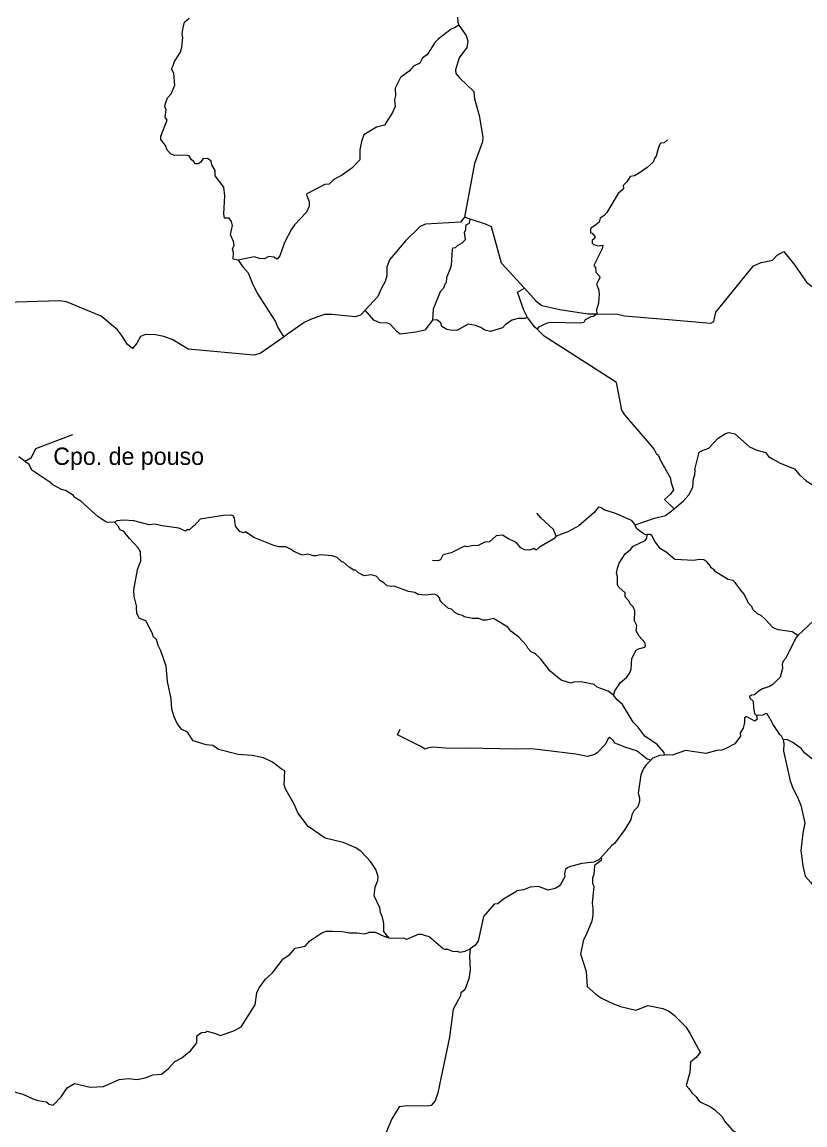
# Model space of a CAD drawing. Extents: x 332 to 501, y 9447 to 9559.
# Drawn here: x 422 to 439.16, y 9472.84 to 9497.01 of the extents above; entities that cross this region are included whole.
import ezdxf

# ---------------------------------------------------------------- set-up
doc = ezdxf.new("R2010")
doc.units = 0
for name, color, linetype in [('Level 1', 7, 'Continuous'), ('Level 13', 7, 'Continuous'), ('Level 4', 7, 'Continuous'), ('Level 5', 7, 'Continuous'), ('Level 6', 7, 'Continuous')]:
    doc.layers.add(name, color=color, linetype=linetype)

msp = doc.modelspace()

# ---------------------------------------------------------------- linework, layer by layer
at = {"layer": 'Level 1'}
msp.add_lwpolyline([(422.3073, 9487.6686), (423.1175, 9487.9761)], dxfattribs=at)
at = {"layer": 'Level 4'}
for points in [[(431.703, 9492.7355), (431.612, 9492.629), (430.848, 9492.58), (430.727, 9492.534), (430.404, 9492.217), (430.059, 9491.799), (429.995, 9491.644), (429.999, 9491.454), (429.96, 9491.327), (429.87, 9491.167), (429.801, 9490.999), (429.5223, 9490.6969)], [(431.8221, 9492.6961), (431.703, 9492.7355)], [(433.0134, 9491.1786), (432.512, 9491.729), (432.294, 9492.524), (432.158, 9492.585), (431.8221, 9492.6961)], [(436.1746, 9490.4947), (437.099, 9490.416), (437.164, 9490.451), (437.208, 9490.657), (438.033, 9491.672), (438.205, 9491.743), (438.45, 9491.794), (438.553, 9491.902), (438.701, 9491.987)], [(438.701, 9491.987), (438.93, 9491.692), (439.195, 9491.311), (439.579, 9491.017), (440.053, 9490.888), (440.224, 9490.896), (440.32, 9490.96), (440.447, 9490.973), (440.528, 9491.006), (440.685, 9491.034), (441.003, 9491.014), (441.1013, 9490.9292)], [(432.9993, 9490.6965), (432.8622, 9491.0926), (433.0134, 9491.1786)], [(433.2741, 9490.8972), (433.0134, 9491.1786)], [(427.6512, 9490.0447), (427.224, 9489.747), (427.082, 9489.71), (425.644, 9489.843), (425.306, 9490.046), (425.109, 9490.118), (424.928, 9490.156), (424.711, 9490.168), (424.596, 9490.12), (424.517, 9489.977), (424.42, 9489.857), (424.303, 9489.951), (424.204, 9490.122), (424.095, 9490.266), (423.738, 9490.569), (422.973, 9490.878), (422.823, 9490.905), (421.883, 9490.873), (421.685, 9490.83), (421.2777, 9490.5303)], [(433.2741, 9490.8972), (433.395, 9490.8), (433.7928, 9490.716)], [(429.5223, 9490.6969), (429.417, 9490.59), (429.301, 9490.549), (428.792, 9490.602), (428.631, 9490.6), (428.358, 9490.511), (428.188, 9490.429), (427.841, 9490.187)], [(433.084, 9490.534), (432.9993, 9490.6965)], [(433.7928, 9490.716), (434.4, 9490.616), (434.599, 9490.617)], [(433.291, 9490.282), (433.24, 9490.328), (433.084, 9490.534)], [(434.599, 9490.617), (434.5292, 9490.5607), (434.4706, 9490.5545), (434.3472, 9490.4836), (434.3164, 9490.4312), (434.2485, 9490.4127), (433.5978, 9490.4281), (433.5145, 9490.4127), (433.3233, 9490.3263), (433.291, 9490.282)], [(434.599, 9490.617), (435.0561, 9490.6121)], [(435.0561, 9490.6121), (435.209, 9490.577), (436.1746, 9490.4947)], [(427.841, 9490.187), (427.763, 9490.125)], [(434.283, 9489.594), (433.448, 9490.131), (433.291, 9490.282)], [(427.7405, 9490.1088), (427.6512, 9490.0447)], [(427.763, 9490.125), (427.7405, 9490.1088)], [(439.4242, 9484.0274), (439.357, 9483.893), (439.0067, 9483.5649)], [(439.0067, 9483.5649), (438.964, 9483.519), (438.746, 9483.068), (438.688, 9483.004), (438.661, 9482.936), (438.67, 9482.845), (438.623, 9482.656), (438.456, 9482.49), (438.385, 9482.446), (438.235, 9482.397), (438.162, 9482.357), (438.054, 9482.268), (437.99, 9482.258), (437.947, 9482.233)], [(437.947, 9482.233), (437.958, 9482.195), (438.031, 9482.126), (438.032, 9481.982), (438.054, 9481.854), (438.104, 9481.816)], [(438.062, 9481.689), (437.907, 9481.777), (437.871, 9481.788), (437.838, 9481.76), (437.834, 9481.657), (437.806, 9481.534), (437.7417, 9481.4371), (437.749, 9481.361), (437.625, 9481.196), (437.441, 9481.095), (437.338, 9481.057), (437.2306, 9481.0486), (436.9892, 9480.9826), (436.5441, 9481.0448), (436.2536, 9480.9448), (436.1392, 9480.9534), (436.0907, 9480.9413)], [(438.115, 9481.735), (438.062, 9481.689)], [(438.104, 9481.816), (438.115, 9481.735)]]:
    msp.add_lwpolyline(points, dxfattribs=at)
at = {"layer": 'Level 5'}
for points in [[(431.575, 9496.947), (431.734, 9496.72), (431.776, 9496.592), (431.751, 9496.458), (431.583, 9496.226), (431.505, 9495.963), (431.508, 9495.889), (431.588, 9495.794), (431.908, 9495.492), (431.918, 9495.329), (432.022, 9494.962), (432.102, 9494.49), (432.093, 9494.388), (431.917, 9493.91), (431.703, 9492.7355)], [(431.549, 9497.12), (431.551, 9497.011), (431.575, 9496.947)], [(426.7398, 9491.795), (426.8441, 9491.6446), (426.9608, 9491.5178), (427.0449, 9491.2991), (427.1588, 9491.0679), (427.5485, 9490.4545), (427.6094, 9490.3176), (427.7405, 9490.1088)], [(435.955, 9487.51), (435.918, 9487.538), (435.855, 9487.654), (435.756, 9487.779), (435.212, 9488.405), (435.147, 9488.507), (435.03, 9489.115), (434.283, 9489.594)], [(437.0545, 9487.6739), (437.261, 9487.889), (437.423, 9487.996), (437.498, 9488.019), (437.626, 9487.985), (437.947, 9487.705), (438.106, 9487.633), (438.298, 9487.578), (438.361, 9487.489), (438.45, 9487.437), (438.621, 9487.348), (438.93, 9487.222), (439.04, 9487.089), (439.19, 9486.956), (439.3183, 9486.8775)], [(422.0718, 9487.3863), (422.2061, 9487.4698), (422.3073, 9487.6686)], [(435.955, 9487.51), (435.9897, 9487.4167), (436.2151, 9487.0187), (436.2234, 9486.9352), (436.2818, 9486.7626), (436.2178, 9486.6624)], [(436.7458, 9487.2087), (436.842, 9487.585), (436.9342, 9487.63)], [(436.9342, 9487.63), (437.0545, 9487.6739)], [(421.9324, 9487.4935), (422.0718, 9487.3863)], [(422.608, 9486.93), (422.219, 9487.193), (422.16, 9487.317), (422.083, 9487.364), (422.0718, 9487.3863)], [(436.7458, 9487.2087), (436.744, 9487.0809), (436.7221, 9487.0188)], [(422.668, 9486.88), (422.608, 9486.93)], [(422.668, 9486.88), (422.872, 9486.765)], [(436.2932, 9486.3408), (436.498, 9486.518), (436.619, 9486.649), (436.703, 9486.821), (436.7221, 9487.0188)], [(424.0299, 9486.0513), (423.8835, 9486.0446), (423.8204, 9486.0628), (423.665, 9486.1759), (423.2872, 9486.508), (423.1459, 9486.5999), (423.1263, 9486.6352), (422.9533, 9486.7447), (422.872, 9486.765)], [(436.2178, 9486.6624), (436.0871, 9486.5507)], [(436.2932, 9486.3408), (436.0871, 9486.5507)], [(435.44, 9485.9942), (435.868, 9486.141), (436.107, 9486.198), (436.2932, 9486.3408)], [(426.1839, 9486.1634), (425.9088, 9486.115), (425.7852, 9485.9773), (425.7393, 9485.9526), (425.6758, 9485.8855), (425.6228, 9485.8855), (425.584, 9485.8573), (425.4356, 9485.9208), (425.0704, 9485.9674), (424.915, 9486.0063), (424.7914, 9485.9922), (424.4519, 9486.0813), (424.2278, 9486.0934), (424.0828, 9486.0772), (424.0299, 9486.0513)], [(433.7124, 9485.743), (433.648, 9485.891), (433.372, 9486.147), (433.289, 9486.246)], [(424.1055, 9485.9601), (424.0299, 9486.0513)], [(424.3547, 9485.6925), (424.2305, 9485.8447), (424.1542, 9485.8808), (424.1055, 9485.9601)], [(424.6036, 9485.2119), (424.6, 9485.4017), (424.5449, 9485.4906), (424.3547, 9485.6925)], [(424.6036, 9485.2119), (424.5232, 9485.0062), (424.4439, 9484.5671), (424.453, 9484.4207), (424.5083, 9484.1853)], [(426.0404, 9481.1714), (425.7492, 9481.2598), (425.6283, 9481.445), (425.5037, 9481.5054), (425.4055, 9481.6358), (425.3357, 9481.784), (425.2866, 9481.9559), (425.2677, 9482.1807), (425.1884, 9482.5616), (425.16, 9482.896), (425.0449, 9483.2275), (424.9844, 9483.3446), (424.9467, 9483.4807), (424.8787, 9483.5449), (424.8598, 9483.6129), (424.7125, 9483.8898), (424.5728, 9483.9427), (424.5161, 9484.0522), (424.5083, 9484.1853)], [(438.338, 9481.85), (438.304, 9481.857), (438.237, 9481.821), (438.104, 9481.816)], [(438.395, 9481.745), (438.338, 9481.85)], [(438.395, 9481.745), (438.473, 9481.596), (438.604, 9481.396), (438.633, 9481.381), (438.684, 9481.282)], [(431.7314, 9481.101), (431.3794, 9481.0933), (431.0095, 9481.1171), (430.911, 9481.1069), (430.8364, 9481.073), (430.7311, 9481.1408), (430.2322, 9481.3886), (430.2899, 9481.5176)], [(434.883, 9481.332), (434.8483, 9481.3072), (434.7872, 9481.1884), (434.6107, 9480.9949), (434.5598, 9480.9576), (434.3935, 9480.9168), (434.1389, 9480.9643), (433.1783, 9481.0865), (432.8457, 9481.0763), (431.7314, 9481.101)], [(435.187, 9481.133), (434.998, 9481.206), (434.964, 9481.261), (434.883, 9481.332)], [(439.3361, 9480.849), (439.1549, 9480.9956), (439.0859, 9481.0819), (438.8961, 9481.22), (438.7667, 9481.289), (438.684, 9481.282)], [(438.684, 9481.282), (438.703, 9481.201), (438.695, 9481.035), (438.841, 9480.38), (438.897, 9480.218), (439.003, 9480.027), (439.069, 9479.849), (439.162, 9479.451), (439.118, 9479.234), (439.076, 9478.852), (439.117, 9478.515), (439.168, 9478.292), (439.287, 9478.161), (439.68, 9477.643), (439.819, 9477.499), (439.824, 9477.462), (439.807, 9477.415), (439.667, 9477.148), (439.447, 9476.881), (439.455, 9476.835)], [(427.7611, 9480.5977), (427.6781, 9480.6414), (427.4928, 9480.7934), (427.2927, 9480.8824), (427.0482, 9480.9342), (426.7407, 9480.9602), (426.3109, 9481.0676), (426.1812, 9481.1566), (426.0404, 9481.1714)], [(435.187, 9481.133), (435.485, 9481.037), (435.707, 9480.867), (435.7944, 9480.8425)], [(435.7944, 9480.8425), (435.682, 9480.73), (435.624, 9480.649), (435.563, 9480.516), (435.504, 9480.109), (435.534, 9480.007), (435.535, 9479.932), (435.496, 9479.813), (435.411, 9479.723), (435.37, 9479.638), (435.347, 9479.532), (435.214, 9479.313), (434.99, 9479.008), (434.928, 9478.966), (434.6848, 9478.6864)], [(436.0907, 9480.9413), (435.975, 9480.935), (435.831, 9480.881), (435.7944, 9480.8425)], [(428.2743, 9479.3782), (428.044, 9479.68), (427.9725, 9479.8528), (427.7819, 9480.1895), (427.7492, 9480.2849), (427.7611, 9480.5977)], [(430.051, 9476.932), (429.931, 9477.0808), (429.9349, 9477.2516), (429.9022, 9477.3945), (429.8605, 9477.4957), (429.8426, 9477.597), (429.7235, 9477.8583), (429.7414, 9478.049), (429.8009, 9478.195), (429.8099, 9478.2844), (429.7592, 9478.4364), (429.6372, 9478.6167), (429.4347, 9478.8312), (429.3186, 9478.9117), (429.0387, 9479.0309), (428.6442, 9479.1283), (428.2743, 9479.3782)], [(434.6848, 9478.6864), (434.645, 9478.647), (434.532, 9478.596), (434.274, 9478.573), (434.021, 9478.506), (433.959, 9478.472), (433.912, 9478.436), (433.893, 9478.349), (433.903, 9478.278), (433.803, 9478.108)], [(434.6848, 9478.6864), (434.704, 9478.677), (434.698, 9478.636), (434.553, 9478.526), (434.536, 9478.327), (434.509, 9478.249), (434.507, 9478.13), (434.532, 9478.076), (434.502, 9477.701), (434.514, 9477.58)], [(433.803, 9478.108), (433.774, 9478.072), (433.685, 9478.021), (433.537, 9477.984), (433.325, 9478.069), (433.138, 9478.052), (432.99, 9477.993), (432.848, 9477.974), (432.823, 9477.945), (432.555, 9477.786), (432.432, 9477.686), (432.351, 9477.675), (432.118, 9477.405), (432.001, 9476.87), (431.925, 9476.77), (431.821, 9476.701)], [(434.514, 9477.58), (434.515, 9477.441), (434.489, 9477.309), (434.367, 9477.005), (434.306, 9476.898), (434.24, 9476.591), (434.367, 9476.199), (434.39, 9475.871), (434.576, 9475.706), (434.706, 9475.617), (434.966, 9475.49), (435.119, 9475.433), (435.456, 9475.355), (435.726, 9475.454), (436.046, 9475.39), (436.172, 9475.343), (436.294, 9475.245), (436.55, 9474.99), (436.643, 9474.849), (436.874, 9474.421), (436.834, 9474.392)], [(425.832, 9474.794), (425.938, 9474.862), (426.03, 9474.876), (426.049, 9474.897), (426.221, 9474.854), (426.354, 9474.797), (426.658, 9474.91), (426.804, 9474.991), (427.115, 9475.474), (427.145, 9475.731), (427.197, 9475.843), (427.336, 9476.037), (427.492, 9476.173), (427.723, 9476.477), (427.871, 9476.578), (427.988, 9476.711), (428.209, 9476.76), (428.312, 9476.875), (428.571, 9477.048), (428.677, 9477.084), (428.804, 9477.089), (429.017, 9477.082), (429.177, 9477.053), (429.351, 9477.05), (429.502, 9477.025), (429.591, 9477.05), (429.597, 9477.064), (429.74, 9477.061), (429.9472, 9476.9661)], [(430.051, 9476.932), (429.9472, 9476.9661)], [(431.341, 9476.685), (431.271, 9476.682), (431.23, 9476.701), (430.928, 9476.963), (430.756, 9477.014), (430.685, 9477.015), (430.426, 9476.901), (430.382, 9476.925), (430.051, 9476.932)], [(431.341, 9476.685), (431.45, 9476.638), (431.534, 9476.645), (431.601, 9476.625), (431.714, 9476.651), (431.821, 9476.701)], [(431.821, 9476.701), (431.807, 9476.539), (431.827, 9476.23), (431.7982, 9476.0396)], [(431.7982, 9476.0396), (431.705, 9475.804), (431.621, 9475.736)], [(431.621, 9475.736), (431.611, 9475.672), (431.452, 9475.377), (431.372, 9474.761), (431.119, 9473.544), (431.056, 9473.366), (430.971, 9473.268), (430.891, 9473.248), (430.441, 9473.261), (430.265, 9473.238), (430.105, 9472.971), (429.88, 9472.435)], [(421.828, 9473.565), (422.021, 9473.515), (422.239, 9473.408), (422.349, 9473.373), (422.538, 9473.346), (422.594, 9473.297), (422.682, 9473.274), (422.861, 9473.456), (422.989, 9473.651), (423.153, 9473.746), (423.497, 9473.668), (423.786, 9473.682), (424.128, 9473.836), (424.332, 9473.857), (424.526, 9473.836), (424.701, 9473.871), (424.866, 9473.934), (425.061, 9473.949), (425.215, 9474.073), (425.354, 9474.227), (425.502, 9474.313), (425.701, 9474.469)], [(436.834, 9474.392), (436.776, 9474.32), (436.651, 9474.212), (436.637, 9473.991), (436.556, 9473.704), (436.621, 9473.64), (436.683, 9473.541), (436.778, 9473.452), (436.849, 9473.355), (437.094, 9473.235), (437.191, 9473.169), (437.345, 9473.015), (437.403, 9472.915), (437.558, 9472.739), (437.659, 9472.666), (437.791, 9472.6), (437.924, 9472.571), (438.22, 9472.553), (438.3854, 9472.491)]]:
    msp.add_lwpolyline(points, dxfattribs=at)
at = {"layer": 'Level 6'}
for points in [[(425.185, 9494.208), (425.146, 9494.306), (425.041, 9494.438), (425.047, 9494.513), (425.184, 9494.861), (425.142, 9494.93), (425.159, 9495.088), (425.132, 9495.16), (425.147, 9495.227), (425.19, 9495.353), (425.272, 9495.44), (425.352, 9495.628), (425.331, 9495.893), (425.276, 9495.989), (425.317, 9496.06), (425.342, 9496.15), (425.476, 9496.352), (425.507, 9496.462), (425.524, 9496.677), (425.511, 9496.756), (425.531, 9496.886), (425.562, 9497.011), (425.665, 9497.102)], [(431.575, 9496.947), (431.484, 9496.884), (431.41, 9496.86), (431.123, 9496.639), (431.05, 9496.562), (430.882, 9496.293), (430.782, 9496.232), (430.724, 9496.112), (430.579, 9496.046), (430.486, 9495.935), (430.301, 9495.799), (430.183, 9495.5669)], [(430.183, 9495.5669), (430.1898, 9495.3993)], [(430.1898, 9495.3993), (430.1669, 9495.3077), (430.177, 9495.159), (430.119, 9495.032), (429.945, 9494.754), (429.773, 9494.713), (429.492, 9494.541), (429.4405, 9494.3934), (429.407, 9494.211), (429.4084, 9493.997), (429.227, 9493.809), (429.027, 9493.663), (428.839, 9493.565), (428.7371, 9493.4631), (428.641, 9493.452), (428.2474, 9493.2471)], [(436.148, 9494.4308), (436.0759, 9494.3686), (436.0039, 9494.3573), (435.9827, 9494.3403), (435.9417, 9494.2442), (435.9035, 9494.0761), (435.8725, 9494.0379), (435.8343, 9493.9418), (435.7071, 9493.826), (435.5178, 9493.6902), (435.4246, 9493.6408), (435.3313, 9493.6295), (435.255, 9493.5108), (435.1745, 9493.4288)], [(426.162, 9493.886), (426.145, 9493.963), (426.067, 9494.022), (425.966, 9494.016), (425.919, 9493.944), (425.862, 9493.904), (425.79, 9493.908), (425.768, 9493.954), (425.713, 9493.994), (425.668, 9494.078), (425.592, 9494.097), (425.348, 9494.086), (425.272, 9494.119), (425.185, 9494.208)], [(426.4255, 9493.393), (426.238, 9493.643), (426.236, 9493.763), (426.162, 9493.886)], [(426.7398, 9491.795), (426.63, 9491.814), (426.635, 9491.962), (426.616, 9492.035), (426.648, 9492.123), (426.634, 9492.205), (426.574, 9492.353), (426.612, 9492.553), (426.594, 9492.644), (426.544, 9492.718), (426.438, 9492.715), (426.423, 9492.811), (426.449, 9493.207), (426.4255, 9493.393)], [(435.1745, 9493.4288), (435.1822, 9493.361), (435.0705, 9493.253), (434.8198, 9492.8369), (434.7619, 9492.7705), (434.6772, 9492.7183), (434.6532, 9492.6294), (434.5458, 9492.5361), (434.4708, 9492.4937), (434.4637, 9492.4612), (434.4609, 9492.3962), (434.5019, 9492.3849), (434.5627, 9492.3029), (434.5288, 9492.2563), (434.4991, 9492.2422), (434.4991, 9492.1644), (434.5288, 9492.1376), (434.6305, 9492.1093), (434.7337, 9492.1206), (434.7153, 9492.04), (434.533, 9491.6768), (434.574, 9491.633), (434.5811, 9491.534), (434.6602, 9491.4464), (434.6659, 9491.4069), (434.5967, 9491.2712), (434.6405, 9491.1553), (434.6518, 9491.0564), (434.6363, 9490.85), (434.5943, 9490.7019), (434.599, 9490.617)], [(428.2474, 9493.2471), (428.239, 9493.223), (428.299, 9493.077), (428.295, 9492.981), (428.237, 9492.847), (427.9763, 9492.5653)], [(431.4932, 9492.0678), (431.5442, 9492.1186), (431.6488, 9492.1721), (431.7227, 9492.2486), (431.7023, 9492.4041), (431.7278, 9492.4679), (431.738, 9492.5698), (431.8094, 9492.6055), (431.8221, 9492.6961)], [(427.9763, 9492.5653), (427.91, 9492.475), (427.754, 9492.178), (427.655, 9491.886), (427.597, 9491.816), (427.524, 9491.858), (427.409, 9491.873), (427.313, 9491.822), (427.205, 9491.833), (427.089, 9491.869), (426.7398, 9491.795)], [(431.4932, 9492.0678), (431.4473, 9492.0551), (431.432, 9492.0271), (431.409, 9491.688), (431.3886, 9491.6013), (431.3071, 9491.4152), (431.2994, 9491.2953), (431.2663, 9491.2673), (431.2382, 9491.178), (431.1643, 9491.0965), (431.0139, 9490.7191), (430.9986, 9490.482)], [(430.2873, 9490.1735), (430.217, 9490.2298), (430.0732, 9490.3928), (430.0189, 9490.4151), (429.8463, 9490.4183), (429.7121, 9490.4759), (429.5223, 9490.6969)], [(430.9986, 9490.482), (430.8303, 9490.2602), (430.6314, 9490.2168), (430.2873, 9490.1735)], [(432.5307, 9490.3106), (432.2682, 9490.2295), (432.1459, 9490.2576), (432.0592, 9490.3162), (431.9394, 9490.3621), (431.7813, 9490.3901), (431.5314, 9490.255), (431.3912, 9490.2576), (431.3147, 9490.2729), (431.2051, 9490.3391), (431.1847, 9490.4207), (431.0955, 9490.487), (430.9986, 9490.482)], [(433.084, 9490.534), (433.0118, 9490.5141), (432.87, 9490.5141), (432.7466, 9490.4771), (432.5955, 9490.3815), (432.5307, 9490.3106)], [(434.7051, 9486.3642), (434.6386, 9486.3809), (434.5443, 9486.2644), (434.206, 9485.9704), (433.9675, 9485.8429), (433.7124, 9485.743)], [(434.7051, 9486.3642), (434.775, 9486.319), (435.022, 9486.244), (435.354, 9486.095), (435.418, 9486.017)], [(428.1242, 9485.3352), (427.9565, 9485.4071), (427.9018, 9485.4516), (427.782, 9485.5098), (427.6314, 9485.5133), (427.5185, 9485.5406), (427.084, 9485.7187), (426.9002, 9485.8375), (426.8454, 9485.8204), (426.777, 9485.8478), (426.6812, 9485.9608), (426.6606, 9486.1423), (426.6298, 9486.1902), (426.5888, 9486.2073), (426.4143, 9486.2005), (426.1839, 9486.1634)], [(435.44, 9485.9942), (435.418, 9486.017)], [(435.702, 9485.779), (435.671, 9485.772), (435.616, 9485.8), (435.47, 9485.914), (435.44, 9485.9942)], [(433.7124, 9485.743), (433.6582, 9485.6878), (433.344, 9485.5055), (433.2739, 9485.4409), (433.2234, 9485.4718), (433.128, 9485.4381), (433.0157, 9485.4437), (432.9372, 9485.4886), (432.8446, 9485.5924), (432.7913, 9485.6289), (432.6651, 9485.685), (432.536, 9485.7664), (432.3957, 9485.7551), (432.2498, 9485.6205), (432.1488, 9485.6093), (432.003, 9485.5419), (431.8599, 9485.5307)], [(434.963, 9482.257), (434.9976, 9482.3516), (435.1217, 9482.5378), (435.2596, 9482.6551), (435.3217, 9482.7516), (435.3562, 9482.8275), (435.37, 9483.062), (435.4665, 9483.2482), (435.5148, 9483.2758), (435.6527, 9483.3102), (435.6665, 9483.3585), (435.6527, 9483.4137), (435.5286, 9483.5516), (435.4596, 9483.6689), (435.4803, 9483.7861), (435.4251, 9483.8895), (435.432, 9484.1102), (435.3976, 9484.193), (435.3286, 9484.262), (435.301, 9484.324), (435.2251, 9484.4137), (435.2183, 9484.5033), (435.0803, 9484.6275), (435.0527, 9484.6757), (435.0527, 9484.8616), (435.032, 9484.9306), (435.0527, 9485.041), (435.0872, 9485.1514), (435.2183, 9485.3585), (435.3424, 9485.4551), (435.3976, 9485.5241), (435.6596, 9485.6483), (435.6941, 9485.7035), (435.702, 9485.779)], [(435.77, 9485.78), (435.702, 9485.779)], [(437.632, 9484.732), (437.587, 9484.77), (437.481, 9484.795), (437.202, 9484.96), (437.17, 9485.004), (437.094, 9485.057), (437.098, 9485.077), (437.015, 9485.182), (436.943, 9485.229), (436.847, 9485.235), (436.729, 9485.211), (436.312, 9485.231), (436.124, 9485.394), (435.997, 9485.47), (435.881, 9485.619), (435.806, 9485.756), (435.77, 9485.78)], [(432.339, 9483.938), (432.1798, 9483.9018), (432.1045, 9483.9018), (432.0156, 9483.9395), (431.8719, 9483.9429), (431.6905, 9483.9737), (431.6529, 9484.0045), (431.5673, 9484.0284), (431.4886, 9484.0729), (431.4168, 9484.1448), (431.3483, 9484.1585), (431.2012, 9484.2919), (431.1601, 9484.3501), (431.1601, 9484.3843), (431.1088, 9484.4459), (431.0369, 9484.4733), (430.8419, 9484.4527), (430.6879, 9484.4664), (430.6126, 9484.5075), (430.4758, 9484.5314), (430.1575, 9484.6478), (430.0994, 9484.6409), (430.007, 9484.658), (429.9351, 9484.723), (429.8564, 9484.7675), (429.7606, 9484.8668), (429.6511, 9484.8941), (429.5005, 9484.8736), (429.3787, 9484.9381), (429.3102, 9484.9963), (429.2726, 9484.9997), (429.1699, 9485.0613), (429.0468, 9485.1743), (429.0091, 9485.1846), (428.9065, 9485.2736), (428.8004, 9485.3147), (428.5369, 9485.3386), (428.4479, 9485.3113), (428.3932, 9485.3113), (428.2666, 9485.3489), (428.1584, 9485.3284), (428.1242, 9485.3352)], [(431.8599, 9485.5307), (431.7589, 9485.5083), (431.714, 9485.5251), (431.6691, 9485.5139), (431.4054, 9485.382), (431.2595, 9485.3455), (431.2287, 9485.3259), (431.1754, 9485.2277), (431.1192, 9485.2025), (431.0014, 9485.2137)], [(437.76, 9484.561), (437.632, 9484.732)], [(438.491, 9483.726), (438.456, 9483.742), (438.285, 9483.931), (438.203, 9484.002), (438.119, 9484.041), (438.018, 9484.137), (437.998, 9484.203), (437.935, 9484.271), (437.824, 9484.479), (437.76, 9484.561)], [(434.546, 9482.49), (434.254, 9482.554), (434.094, 9482.541), (434.032, 9482.521), (433.821, 9482.59), (433.577, 9482.786), (433.38, 9483.041), (433.257, 9483.166), (433.161, 9483.209), (433.09, 9483.287), (433.057, 9483.35), (432.888, 9483.531), (432.714, 9483.66), (432.65, 9483.752), (432.339, 9483.938)], [(439.0067, 9483.5649), (438.882, 9483.644), (438.579, 9483.692), (438.491, 9483.726)], [(434.963, 9482.257), (434.846, 9482.346), (434.611, 9482.432), (434.546, 9482.49)], [(436.0907, 9480.9413), (436.071, 9481.011), (435.921, 9481.176), (435.654, 9481.362), (435.499, 9481.562), (435.395, 9481.665), (435.161, 9482.055), (435.043, 9482.155), (434.963, 9482.257)], [(425.701, 9474.469), (425.8331, 9474.6362), (425.832, 9474.794)]]:
    msp.add_lwpolyline(points, dxfattribs=at)

# ---------------------------------------------------------------- texts
at = {"layer": 'Level 13'}
msp.add_text('Cpo. de pouso', height=0.38, dxfattribs=at).set_placement((422.6855, 9487.3066))

doc.saveas('drawing.dxf')
